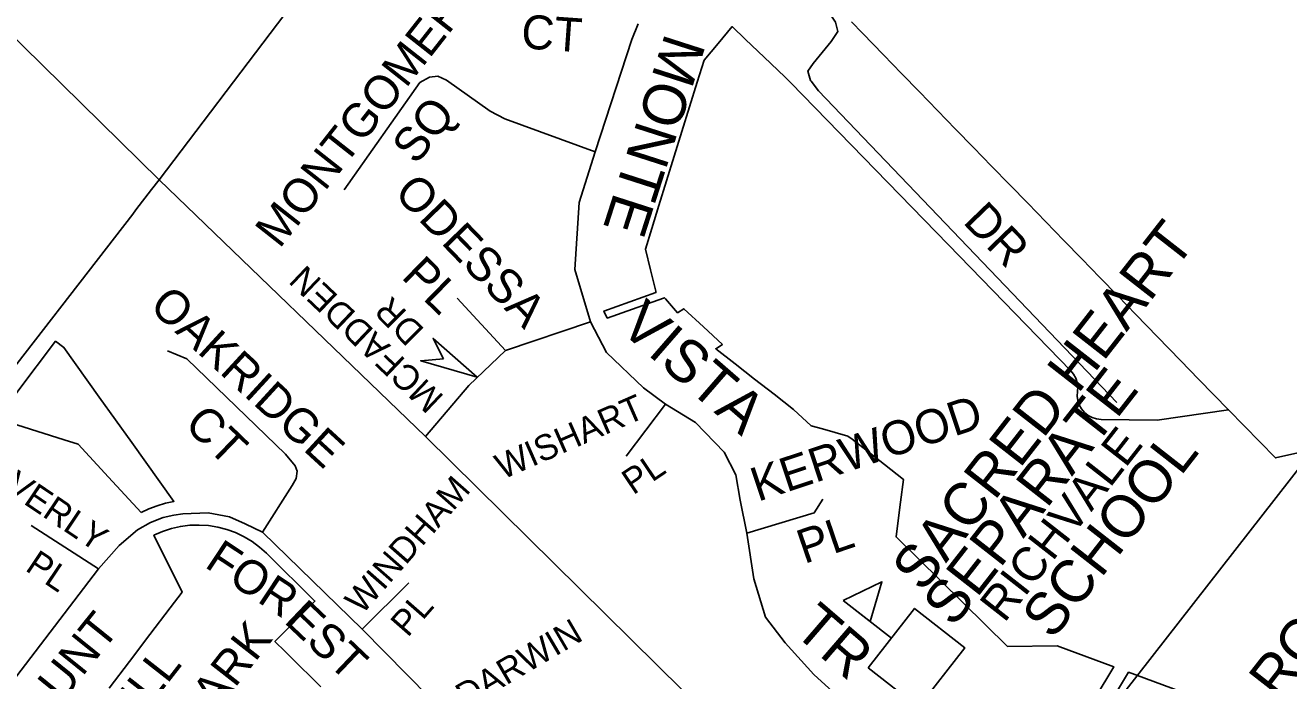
# Model space of a CAD drawing. Extents: x 586326 to 623965, y 4819854 to 4857850.
# Drawn here: x 596261 to 597005, y 4842923 to 4843309 of the extents above; entities that cross this region are included whole.
import ezdxf

# ---------------------------------------------------------------- set-up
doc = ezdxf.new("R2010")
doc.units = 0
for name, color, linetype in [('Lots_Concessions', 7, 'Continuous'), ('Major Rds and Hwys', 7, 'Continuous'), ('Minor Rd Lbls', 7, 'Continuous'), ('Minor Rds', 7, 'Continuous'), ('Park Lbls', 7, 'Continuous'), ('Park Outlines', 7, 'Continuous'), ('Proposed Secondary Rds', 7, 'Continuous'), ('School Syms_Lbls', 7, 'Continuous')]:
    doc.layers.add(name, color=color, linetype=linetype)

msp = doc.modelspace()

# ---------------------------------------------------------------- linework, layer by layer
at = {"layer": 'Lots_Concessions'}
msp.add_line((596795.81, 4842771.49), (597203.27, 4843294.42), dxfattribs=at)
at = {"layer": 'Major Rds and Hwys'}
for points in [[(596340.29, 4843218.09), (596156.73, 4843398.36)], [(596497.11, 4843066.96), (596340.29, 4843218.09)], [(596739.26, 4842827.72), (596497.11, 4843066.96)]]:
    msp.add_lwpolyline(points, dxfattribs=at)
at = {"layer": 'Minor Rd Lbls'}
for p, q in [((596501.53, 4843124.68), (596527.47, 4843101.82)), ((596507.76, 4843112.68), (596501.53, 4843124.68)), ((596494.29, 4843111.54), (596507.76, 4843112.68)), ((596527.47, 4843101.82), (596494.29, 4843111.54)), ((596507.76, 4843112.68), (596507.76, 4843112.68))]:
    msp.add_line(p, q, dxfattribs=at)
msp.add_lwpolyline([(596507.76, 4843112.68), (596501.53, 4843124.68), (596527.47, 4843101.82), (596494.29, 4843111.54)], close=True, dxfattribs=at)
at = {"layer": 'Minor Rds'}
for points in [[(596676.39, 4843371.97), (596733.88, 4843317.9), (596738.53, 4843310.85), (596740, 4843305.42), (596736.04, 4843299.55), (596725.3, 4843286.61), (596722.35, 4843282.02), (596723.78, 4843276.54), (596724.16, 4843276.05)], [(596597.01, 4843234.48), (596618.59, 4843300.6), (596622.4, 4843309.86)], [(596597.01, 4843234.48), (596543.72, 4843253.98), (596535.23, 4843258.55), (596509.53, 4843276.81), (596504.31, 4843279.07), (596499.39, 4843278.46), (596493.81, 4843275.37), (596449.26, 4843212.24)], [(596724.16, 4843276.05), (596728.53, 4843270.44), (596904.28, 4843086.89)], [(596594.32, 4843134.48), (596585, 4843165.33), (596587.63, 4843204.61), (596597.01, 4843234.48)], [(596544.26, 4843117.6), (596515.73, 4843148.45)], [(596594.32, 4843134.48), (596544.26, 4843117.6)], [(596638.35, 4843085.99), (596625.51, 4843095.54), (596603.63, 4843116.43), (596594.32, 4843134.48)], [(596401.06, 4843010.49), (596418.5, 4843038.12), (596420.84, 4843042.16), (596421.52, 4843046.52), (596420.23, 4843049.58), (596414.64, 4843056.53), (596356.57, 4843112.69), (596345.13, 4843117.32)], [(596544.26, 4843117.6), (596522.61, 4843097.02), (596497.11, 4843066.96)], [(596638.35, 4843085.99), (596615.27, 4843055.31)], [(596686.29, 4843009.91), (596682.38, 4843029.46), (596679.88, 4843044.25), (596672.9, 4843057.64), (596656.02, 4843075.11), (596638.35, 4843085.99)], [(596686.29, 4843009.91), (596726.08, 4843022.04), (596731.03, 4843030)], [(596401.06, 4843010.49), (596390.92, 4843015.48), (596381.6, 4843019.55), (596369.09, 4843021.88), (596354.24, 4843021.3), (596348.86, 4843020.63), (596342.53, 4843019.24), (596335.11, 4843016.19), (596327.4, 4843011.99), (596316.7, 4843002.67), (596304.43, 4842988.96)], [(596304.43, 4842988.96), (596264.85, 4843014.57)], [(596459.85, 4842953.45), (596401.06, 4843010.49)], [(596785.24, 4842872.54), (596725.87, 4842926.67), (596708.99, 4842945.3), (596697.35, 4842960.43), (596690.36, 4842983.14), (596686.29, 4843009.91)], [(596304.43, 4842988.96), (596244.13, 4842910.33)], [(596459.85, 4842953.45), (596487.21, 4842980.81)], [(596516.9, 4842889.42), (596499.44, 4842913.28), (596459.85, 4842953.45)]]:
    msp.add_lwpolyline(points, dxfattribs=at)
at = {"layer": 'Park Outlines'}
for points in [[(596747.96, 4843310.99), (596754.43, 4843304.34), (596766.79, 4843291.63), (596777.42, 4843280.7), (596788.04, 4843269.78), (596798.66, 4843258.86), (596809.28, 4843247.94), (596819.9, 4843237.02), (596830.52, 4843226.09), (596841.14, 4843215.17), (596851.77, 4843204.25), (596862.39, 4843193.33), (596873.01, 4843182.41), (596883.63, 4843171.48), (596894.25, 4843160.56), (596904.87, 4843149.64), (596915.5, 4843138.72), (596928.25, 4843125.6), (596941.84, 4843111.63), (596952.63, 4843100.53), (596970.05, 4843082.61), (596997.65, 4843054.24), (597183.91, 4843095.91)], [(597183.91, 4843095.91), (596997.65, 4843054.24), (596970.05, 4843082.61), (596927.95, 4843076.53), (596895.02, 4843076.98), (596892.32, 4843077.28), (596889.73, 4843078.08), (596887.33, 4843079.35), (596885.22, 4843081.05), (596883.46, 4843083.12), (596882.13, 4843085.48), (596881.27, 4843088.05), (596880.91, 4843090.74), (596881.06, 4843093.45), (596881.21, 4843096.08), (596880.88, 4843098.7), (596880.07, 4843101.21), (596878.82, 4843103.53), (596877.16, 4843105.58), (596804.88, 4843179.91), (596712.31, 4843275.1), (596708.66, 4843278.6), (596696.57, 4843290.2), (596685.57, 4843300.75), (596677.74, 4843308.25), (596669.44, 4843298.38), (596661.2, 4843288.58), (596657.17, 4843275.63), (596652.65, 4843261.08), (596648.13, 4843246.53), (596643.6, 4843231.98), (596639.08, 4843217.43), (596634.56, 4843202.88), (596630.33, 4843189.29), (596626.6, 4843177.3), (596629.57, 4843165.04), (596632.64, 4843152.39), (596632.82, 4843151.64), (596602.16, 4843140.76), (596604.15, 4843136.62), (596633.91, 4843147.18), (596637.91, 4843148.6), (596638.45, 4843147.98), (596645.59, 4843139.76), (596649.3, 4843142.17), (596660.8, 4843131.48), (596671.96, 4843121.1), (596668.06, 4843118.57), (596679.5, 4843109.64), (596690.93, 4843100.72), (596702.37, 4843091.8), (596713.8, 4843082.88), (596724.16, 4843073.25), (596730.91, 4843071.36), (596745.88, 4843067.18), (596748.27, 4843065.3), (596759.07, 4843056.85), (596767.37, 4843050.35), (596778.51, 4843041.63), (596776.82, 4843028.21), (596776.64, 4843026.82), (596774.25, 4843007.8), (596839.91, 4842943.14), (596869.12, 4842943.61), (596902.46, 4842931.28), (596879.96, 4842893.79)], [(596435.36, 4842919.5), (596428.86, 4842925.92), (596423.62, 4842931.09), (596422.35, 4842932.35), (596414.33, 4842940.26), (596408.36, 4842946.16), (596431.9, 4842970.01), (596403.45, 4842998.1), (596399.35, 4843001.78), (596394.91, 4843005.05), (596390.18, 4843007.89), (596385.21, 4843010.27), (596380.03, 4843012.16), (596374.69, 4843013.55), (596369.25, 4843014.43), (596363.75, 4843014.78), (596358.24, 4843014.61), (596355.5, 4843014.26), (596352.77, 4843013.92), (596347.39, 4843012.7), (596342.15, 4843010.99), (596337.1, 4843008.78), (596353.74, 4842975.22), (596346.77, 4842966.04), (596334.8, 4842950.26), (596322.82, 4842934.49), (596310.85, 4842918.71)], [(596888.05, 4842889.51), (596911.18, 4842928.06), (596941.31, 4842916.91)]]:
    msp.add_lwpolyline(points, dxfattribs=at)
msp.add_lwpolyline([(596329.57, 4843022.05), (596334.21, 4843024.21), (596338.99, 4843026.05), (596343.88, 4843027.54), (596348.87, 4843028.69), (596324.07, 4843063.39), (596304.95, 4843090.14), (596284.09, 4843119.33), (596279.23, 4843123.01), (596256.97, 4843093.68), (596245.91, 4843079.11), (596250.77, 4843075.43), (596256.39, 4843073.67), (596284.35, 4843064.93), (596292.49, 4843062.39), (596310.43, 4843042.87)], close=True, dxfattribs=at)
at = {"layer": 'Proposed Secondary Rds'}
for points in [[(596340.29, 4843218.09), (596549.24, 4843493.83)], [(596234.69, 4843082.09), (596324.62, 4843197.92), (596326.53, 4843200.37), (596335.78, 4843212.28), (596340.29, 4843218.09)]]:
    msp.add_lwpolyline(points, dxfattribs=at)
at = {"layer": 'School Syms_Lbls'}
msp.add_line((596771.48, 4842948.17), (596743.07, 4842970.37), dxfattribs=at)
for points in [[(596743.07, 4842970.37), (596765.85, 4842981.4), (596758.94, 4842957.9)], [(596757.85, 4842930.72), (596785.12, 4842965.62), (596814.72, 4842942.49), (596787.46, 4842907.59)]]:
    msp.add_lwpolyline(points, close=True, dxfattribs=at)

# ---------------------------------------------------------------- texts
at = {"layer": 'Minor Rd Lbls'}
for s, height, rotation, p in [('MONTGOMERY', 19.998, 51.78899, (596411.11, 4843177.06)), ('CT', 19.998, 355.9144, (596552.98, 4843295.6)), ('MONTE', 25.002, 252.18113, (596638.47, 4843305.1)), ('SQ', 19.998, 51.78899, (596491.65, 4843226.32)), ('ODESSA', 19.998, 314.02799, (596477.89, 4843209.65)), ('DR', 19.998, 313.96466, (596813.01, 4843192.95)), ('PL', 19.998, 315.6903, (596482.23, 4843160.44)), ('MCFADDEN', 15, 136.47603, (596508.53, 4843090.35)), ('OAKRIDGE', 19.998, 317.41026, (596333.66, 4843142.61)), ('DR', 15, 134.95146, (596497.04, 4843129.74)), ('VISTA', 25.002, 318.99093, (596610.48, 4843130.1)), ('WISHART', 15, 23.6294, (596542.45, 4843041.35)), ('KERWOOD', 19.998, 18.3912, (596692.82, 4843028.37)), ('CT', 19.998, 315.97241, (596354.25, 4843073.07)), ('WAVERLY', 15, 326.05643, (596221.82, 4843053.21)), ('PL', 15, 34.01937, (596619.38, 4843032.19)), ('WINDHAM', 15, 48.70738, (596459.67, 4842961.51)), ('PL', 19.998, 18.83766, (596720.15, 4842991.75)), ('FOR', 19.998, 326.5111, (596366.35, 4842990.43)), ('PL', 15, 326.05643, (596260.71, 4842988.34)), ('EST', 19.998, 316.37995, (596413.14, 4842957.74)), ('PL', 15, 48.85771, (596486.58, 4842948.16)), ('TR', 25.002, 319.23123, (596712.82, 4842951.57)), ('MOUNT ', 19.998, 51.14977, (596255.81, 4842876.54)), ('DARWIN', 15, 30.4111, (596520.61, 4842906.19))]:
    msp.add_text(s, height=height, rotation=rotation, dxfattribs=at).set_placement(p)
at = {"layer": 'Park Lbls'}
for s, p in [('RICHVALE', (596837.98, 4842956.66)), ('PARK', (596362.83, 4842890.37)), ('CANTRILL', (596274.52, 4842830.7))]:
    msp.add_text(s, height=19.992, rotation=52.00002, dxfattribs=at).set_placement(p)
at = {"layer": 'School Syms_Lbls'}
for s, p in [('ROBERT H. LAGERQUIST SR.', (597000.08, 4842910.2)), ('SACRED HEART', (596789.84, 4842974.46)), ('SEPARATE', (596807.99, 4842953.79)), ('SCHOOL', (596866.36, 4842946.5))]:
    msp.add_text(s, height=25, rotation=52.00002, dxfattribs=at).set_placement(p)

doc.saveas('drawing.dxf')
